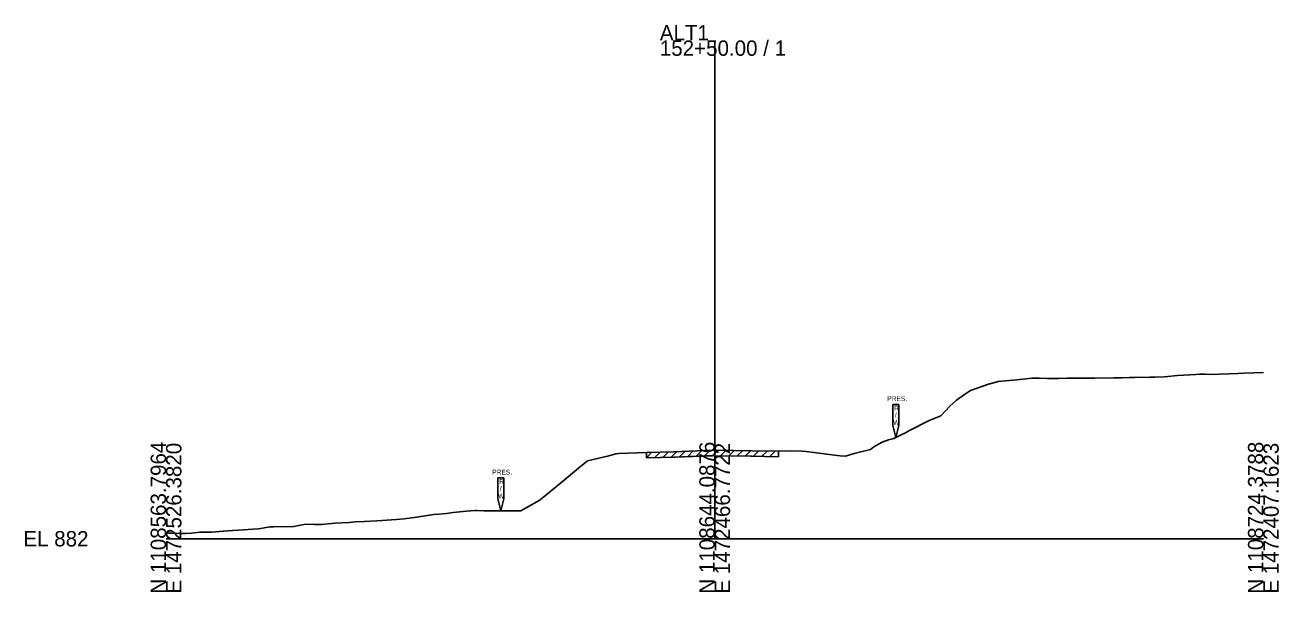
# Model space of a CAD drawing. Extents: x -26 to 2203, y -10 to 19568.
# Drawn here: x -25.7 to 202.8, y 14490.3 to 14593.6 of the extents above; entities that cross this region are included whole.
import ezdxf

# ---------------------------------------------------------------- set-up
doc = ezdxf.new("R2010")
doc.units = 0
for name, color, linetype in [('RD_GPK_XS_Cell', 7, 'Continuous'), ('RD_XS_ExGround', 7, 'Continuous'), ('RD_XS_ExPaveRet', 7, 'Continuous'), ('RD_XS_ExRW', 7, 'Continuous')]:
    doc.layers.add(name, color=color, linetype=linetype)

msp = doc.modelspace()

# ---------------------------------------------------------------- linework, layer by layer
at = {"layer": 'RD_GPK_XS_Cell'}
for p, q in [((100, 14500), (100, 14590.83)), ((0, 14500), (100, 14500)), ((100, 14500), (200, 14500))]:
    msp.add_line(p, q, dxfattribs=at)
at = {"layer": 'RD_XS_ExGround'}
msp.add_lwpolyline([(0, 14501.04), (1.05, 14501.01), (2.61, 14500.98), (3.57, 14500.96), (4.61, 14501.01), (6.14, 14501.21), (8.35, 14501.19), (10.43, 14501.4), (12.09, 14501.49), (13.22, 14501.59), (15.82, 14501.77), (16.86, 14501.83), (18.26, 14502.04), (19, 14502.16), (19.56, 14502.17), (23.29, 14502.26), (25.44, 14502.64), (27.03, 14502.58), (27.58, 14502.57), (28.32, 14502.62), (30.77, 14502.85), (33.35, 14502.99), (34.01, 14503.01), (34.5, 14503.07), (36.16, 14503.17), (38.39, 14503.29), (41.98, 14503.49), (43.42, 14503.63), (44.74, 14503.79), (45.71, 14503.92), (47.6, 14504.26), (48.84, 14504.4), (49.73, 14504.51), (51.13, 14504.61), (52.34, 14504.77), (53.56, 14504.89), (54.77, 14505.04), (56.32, 14505.14), (56.69, 14505.14), (57.92, 14505.1), (59.51, 14505.07), (59.95, 14505.07), (64.25, 14505.09), (64.67, 14505.1), (67.99, 14506.99), (68.58, 14507.38), (71.87, 14510.14), (72.61, 14510.76), (75.17, 14512.84), (76.8, 14514.21), (80.71, 14515.13), (81.99, 14515.46), (82.55, 14515.51), (87.56, 14515.73), (92.53, 14515.87), (99.62, 14516.13), (100, 14516.12), (106.83, 14516.03), (111.65, 14515.94), (113.97, 14516.02), (115.96, 14515.99), (116.7, 14515.88), (122.33, 14515.18), (122.9, 14515.09), (123.86, 14515.08), (124.65, 14515.29), (125.42, 14515.54), (128.37, 14516.29), (128.98, 14516.77), (130.51, 14517.61), (131.65, 14518.05), (132.65, 14518.29), (134.01, 14518.96), (134.8, 14519.3), (135.39, 14519.7), (139.12, 14521.56), (141.23, 14522.38), (142.86, 14524.16), (144.07, 14525.26), (145.52, 14526.31), (146.6, 14527.02), (149.9, 14528.15), (151.03, 14528.48), (151.69, 14528.69), (155.06, 14528.99), (157.81, 14529.3), (159.17, 14529.26), (160.53, 14529.24), (161.54, 14529.22), (162.68, 14529.23), (164.2, 14529.25), (164.82, 14529.26), (165.28, 14529.27), (166.96, 14529.3), (169.24, 14529.29), (172.75, 14529.34), (173.4, 14529.34), (174.27, 14529.36), (175.54, 14529.39), (176.49, 14529.41), (179.3, 14529.45), (179.83, 14529.46), (180.22, 14529.48), (181.98, 14529.53), (184.34, 14529.78), (187.7, 14529.94), (188.41, 14530.01), (189.37, 14530), (190.34, 14529.92), (195.36, 14530.14), (196.53, 14530.17), (200, 14530.28)], dxfattribs=at)
at = {"layer": 'RD_XS_ExPaveRet'}
for p, q in [((87.56, 14514.75), (88.56, 14515.76)), ((87.56, 14514.75), (87.56, 14515.73)), ((87.56, 14515.73), (87.56, 14514.73)), ((87.56, 14514.75), (92.75, 14514.9)), ((87.56, 14514.73), (92.53, 14514.87)), ((89.06, 14514.8), (90.06, 14515.8)), ((90.56, 14514.84), (91.56, 14515.84)), ((92.06, 14514.88), (93.07, 14515.89)), ((92.53, 14514.87), (99.62, 14515.13)), ((92.75, 14514.9), (99.62, 14515.15)), ((93.56, 14514.91), (94.6, 14515.95)), ((95.06, 14514.96), (96.1, 14516)), ((96.56, 14515.02), (97.6, 14516.05)), ((98.06, 14515.07), (99.1, 14516.11)), ((99.56, 14515.12), (100.55, 14516.11)), ((99.62, 14515.15), (100, 14515.14)), ((100, 14515.14), (106.61, 14515.05)), ((100, 14515.12), (106.83, 14515.03)), ((101.06, 14515.11), (102.05, 14516.09)), ((102.56, 14515.09), (103.55, 14516.07)), ((104.06, 14515.07), (105.05, 14516.05)), ((105.56, 14515.05), (106.55, 14516.03)), ((106.61, 14515.05), (111.64, 14514.96)), ((106.83, 14515.03), (111.65, 14514.94)), ((107.06, 14515.03), (108.04, 14516.01)), ((108.56, 14515), (109.54, 14515.98)), ((110.06, 14514.97), (111.04, 14515.95)), ((111.64, 14514.96), (111.65, 14514.96)), ((111.65, 14515.96), (111.65, 14514.96)), ((111.65, 14515.94), (111.65, 14514.94))]:
    msp.add_line(p, q, dxfattribs=at)
at = {"layer": 'RD_XS_ExRW'}
for points in [[(132.45, 14524.47), (133.55, 14524.47), (133.55, 14520.64), (133, 14518.46), (132.45, 14520.64)], [(60.45, 14511.08), (61.55, 14511.08), (61.55, 14507.26), (61, 14505.07), (60.45, 14507.26)]]:
    msp.add_lwpolyline(points, close=True, dxfattribs=at)

# ---------------------------------------------------------------- texts
at = {"layer": 'RD_GPK_XS_Cell'}
for s, p in [('ALT1', (90, 14590.83)), ('152+50.00 / 1', (90, 14588.03)), ('EL 882', (-26, 14498.6))]:
    msp.add_text(s, height=2.8, dxfattribs=at).set_placement(p)
for s, p in [('N 1108563.7964', (0, 14490)), ('E 1472526.3820', (2.8, 14490)), ('N 1108644.0876', (100, 14490)), ('E 1472466.7722', (102.8, 14490)), ('N 1108724.3788', (200, 14490)), ('E 1472407.1623', (202.8, 14490))]:
    msp.add_text(s, height=2.8, rotation=90, dxfattribs=at).set_placement(p)
at = {"layer": 'RD_XS_ExRW'}
for s, p in [('PRES.', (131.45, 14525.1)), ('R', (132.71, 14523.38)), ('W', (132.53, 14520.75)), ('/', (132.83, 14522.07)), ('PRES.', (59.45, 14511.71)), ('R', (60.71, 14509.99)), ('/', (60.83, 14508.68)), ('W', (60.53, 14507.37))]:
    msp.add_text(s, height=0.875, dxfattribs=at).set_placement(p)

doc.saveas('drawing.dxf')
